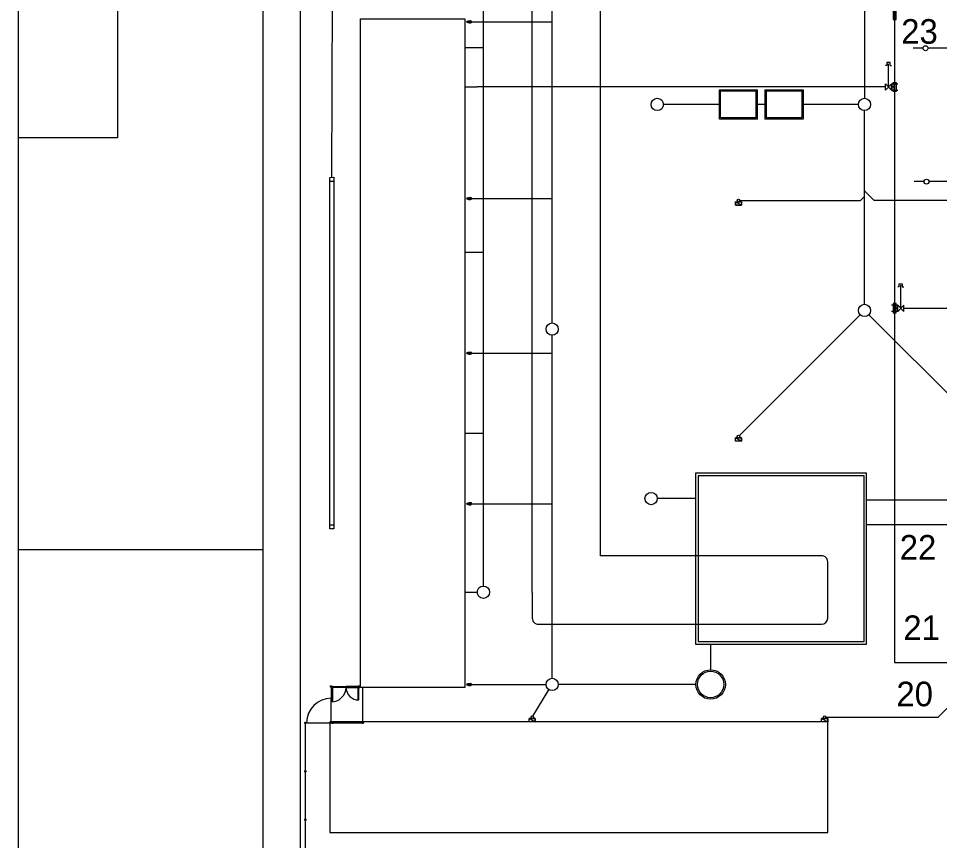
# Model space of a CAD drawing. Extents: x -263995 to -263575, y -1242437 to -1242140.
# Drawn here: x -263995.4 to -263920.5, y -1242264.6 to -1242197.8 of the extents above; entities that cross this region are included whole.
import ezdxf

# ---------------------------------------------------------------- set-up
doc = ezdxf.new("R2010")
doc.units = 0
for name, color, linetype in [('KFA_2D_SITUACIA_DSP', 7, 'Continuous'), ('KFA_BODY', 7, 'Continuous'), ('RAM_NA_TLAC_A3_1-1000', 7, 'Continuous')]:
    doc.layers.add(name, color=color, linetype=linetype)

msp = doc.modelspace()

# ---------------------------------------------------------------- linework, layer by layer
at = {"layer": 'KFA_2D_SITUACIA_DSP'}
for p, q in [((-263953.617, -1242244.458), (-263953.617, -1242140.046)), ((-263948.093, -1242140.046), (-263948.093, -1242241.458)), ((-263926.593, -1242155.252), (-263926.593, -1242204.252)), ((-263952, -1242222.527), (-263952, -1242182)), ((-263924.143, -1242185.14), (-263924.143, -1242250.14)), ((-263972.468, -1242294.032), (-263972.468, -1242187.932)), ((-263987.358, -1242190.982), (-263987.358, -1242207.482)), ((-263975.518, -1242290.982), (-263975.518, -1242190.982)), ((-263957.597, -1242243.932), (-263957.597, -1242193.383)), ((-263969.921, -1242210.683), (-263969.869, -1242195.133)), ((-263924.268, -1242197.107), (-263924.268, -1242197.857)), ((-263924.018, -1242197.857), (-263924.018, -1242197.107)), ((-263967.597, -1242197.782), (-263959.097, -1242197.782)), ((-263967.597, -1242252.182), (-263967.597, -1242197.782)), ((-263967.593, -1242252.182), (-263967.593, -1242197.782)), ((-263967.593, -1242197.782), (-263959.093, -1242197.782)), ((-263967.593, -1242197.782), (-263959.097, -1242197.782)), ((-263967.593, -1242252.182), (-263967.593, -1242197.782)), ((-263967.478, -1242197.782), (-263967.358, -1242197.782)), ((-263959.097, -1242197.782), (-263959.093, -1242252.182)), ((-263959.097, -1242197.782), (-263959.097, -1242252.182)), ((-263959.093, -1242197.782), (-263959.093, -1242252.182)), ((-263958.762, -1242197.962), (-263958.742, -1242197.942)), ((-263958.742, -1242197.942), (-263958.637, -1242197.942)), ((-263924.268, -1242197.857), (-263924.018, -1242197.857)), ((-263958.799, -1242197.962), (-263958.762, -1242197.962)), ((-263958.799, -1242198.102), (-263958.762, -1242198.102)), ((-263958.762, -1242198.102), (-263958.742, -1242198.122)), ((-263958.742, -1242198.122), (-263958.637, -1242198.122)), ((-263958.575, -1242198.032), (-263952, -1242198.032)), ((-263959.097, -1242200.132), (-263957.597, -1242200.132)), ((-263921.824, -1242200.182), (-263922.624, -1242200.182)), ((-263915.293, -1242200.182), (-263921.424, -1242200.182)), ((-263924.768, -1242201.582), (-263924.893, -1242201.582)), ((-263924.768, -1242201.332), (-263924.768, -1242201.582)), ((-263924.518, -1242201.332), (-263924.768, -1242201.332)), ((-263924.643, -1242203.332), (-263924.643, -1242201.457)), ((-263924.518, -1242201.582), (-263924.518, -1242201.332)), ((-263924.518, -1242201.582), (-263924.393, -1242201.582)), ((-263924.893, -1242203.582), (-263924.893, -1242203.082)), ((-263924.393, -1242203.082), (-263924.893, -1242203.582)), ((-263924.893, -1242203.082), (-263924.393, -1242203.582)), ((-263924.393, -1242203.582), (-263924.393, -1242203.082)), ((-263924.393, -1242203.082), (-263923.893, -1242203.082)), ((-263924.268, -1242203.707), (-263924.268, -1242202.957)), ((-263924.268, -1242202.957), (-263924.018, -1242202.957)), ((-263924.018, -1242202.957), (-263924.018, -1242203.707)), ((-263959.097, -1242203.332), (-263958.097, -1242203.332)), ((-263924.893, -1242203.332), (-263958.097, -1242203.332)), ((-263938.393, -1242203.552), (-263935.293, -1242203.552)), ((-263938.393, -1242205.952), (-263938.393, -1242203.552)), ((-263938.293, -1242205.852), (-263938.293, -1242203.652)), ((-263938.293, -1242203.652), (-263935.393, -1242203.652)), ((-263935.393, -1242205.852), (-263935.393, -1242203.652)), ((-263935.293, -1242205.952), (-263935.293, -1242203.552)), ((-263934.693, -1242203.552), (-263931.593, -1242203.552)), ((-263934.693, -1242203.552), (-263934.693, -1242205.952)), ((-263934.593, -1242203.652), (-263934.593, -1242205.852)), ((-263934.593, -1242203.652), (-263931.693, -1242203.652)), ((-263931.693, -1242203.652), (-263931.693, -1242205.852)), ((-263931.593, -1242203.552), (-263931.593, -1242205.952)), ((-263924.143, -1242203.332), (-263924.393, -1242203.332)), ((-263924.393, -1242203.332), (-263924.143, -1242203.332)), ((-263924.393, -1242203.582), (-263923.893, -1242203.582)), ((-263924.018, -1242203.707), (-263924.268, -1242203.707)), ((-263938.393, -1242204.752), (-263942.945, -1242204.752)), ((-263934.693, -1242204.752), (-263935.293, -1242204.752)), ((-263927.093, -1242204.752), (-263931.593, -1242204.752)), ((-263926.593, -1242221.011), (-263926.593, -1242205.252)), ((-263935.293, -1242205.952), (-263938.393, -1242205.952)), ((-263935.393, -1242205.852), (-263938.293, -1242205.852)), ((-263931.593, -1242205.952), (-263934.693, -1242205.952)), ((-263931.693, -1242205.852), (-263934.593, -1242205.852)), ((-263987.358, -1242207.482), (-263995.414, -1242207.482)), ((-263970.071, -1242210.684), (-263969.77, -1242210.682)), ((-263970.07, -1242239.282), (-263970.071, -1242210.684)), ((-263969.77, -1242210.682), (-263969.77, -1242239.282)), ((-263970.071, -1242210.983), (-263969.771, -1242210.985)), ((-263921.751, -1242211.032), (-263922.551, -1242211.032)), ((-263903.343, -1242211.032), (-263921.351, -1242211.032)), ((-263925.798, -1242212.562), (-263926.593, -1242211.767)), ((-263958.799, -1242212.337), (-263958.762, -1242212.337)), ((-263958.799, -1242212.477), (-263958.762, -1242212.477)), ((-263958.762, -1242212.337), (-263958.742, -1242212.317)), ((-263958.762, -1242212.477), (-263958.742, -1242212.497)), ((-263958.742, -1242212.317), (-263958.637, -1242212.317)), ((-263958.742, -1242212.497), (-263958.637, -1242212.497)), ((-263958.575, -1242212.407), (-263952, -1242212.407)), ((-263937.093, -1242212.952), (-263937.093, -1242212.662)), ((-263937.093, -1242212.662), (-263936.593, -1242212.662)), ((-263936.593, -1242212.952), (-263937.093, -1242212.662)), ((-263936.593, -1242212.952), (-263937.093, -1242212.662)), ((-263937.093, -1242212.662), (-263937.093, -1242212.952)), ((-263936.743, -1242212.562), (-263926.919, -1242212.562)), ((-263936.593, -1242212.662), (-263936.593, -1242212.952)), ((-263926.919, -1242212.562), (-263926.593, -1242212.237)), ((-263916.443, -1242212.562), (-263925.798, -1242212.562)), ((-263936.593, -1242212.952), (-263937.093, -1242212.952)), ((-263937.093, -1242212.952), (-263936.593, -1242212.952)), ((-263959.097, -1242216.782), (-263957.597, -1242216.782)), ((-263923.768, -1242219.582), (-263923.893, -1242219.582)), ((-263923.768, -1242219.582), (-263923.768, -1242219.332)), ((-263923.768, -1242219.332), (-263923.518, -1242219.332)), ((-263923.643, -1242221.332), (-263923.643, -1242219.457)), ((-263923.518, -1242219.332), (-263923.518, -1242219.582)), ((-263923.518, -1242219.582), (-263923.393, -1242219.582)), ((-263923.893, -1242221.082), (-263924.393, -1242221.082)), ((-263924.018, -1242220.957), (-263924.268, -1242220.957)), ((-263924.268, -1242220.957), (-263924.268, -1242221.707)), ((-263924.018, -1242221.707), (-263924.018, -1242220.957)), ((-263923.893, -1242221.582), (-263923.893, -1242221.082)), ((-263923.893, -1242221.082), (-263923.393, -1242221.582)), ((-263923.393, -1242221.082), (-263923.893, -1242221.582)), ((-263923.393, -1242221.582), (-263923.393, -1242221.082)), ((-263936.772, -1242231.691), (-263926.947, -1242221.865)), ((-263916.414, -1242231.691), (-263926.24, -1242221.865)), ((-263923.893, -1242221.582), (-263924.393, -1242221.582)), ((-263924.268, -1242221.707), (-263924.018, -1242221.707)), ((-263924.143, -1242221.332), (-263923.893, -1242221.332)), ((-263923.893, -1242221.332), (-263924.143, -1242221.332)), ((-263923.393, -1242221.332), (-263903.343, -1242221.332)), ((-263952, -1242251.432), (-263952, -1242223.527)), ((-263958.799, -1242224.912), (-263958.762, -1242224.912)), ((-263958.762, -1242224.912), (-263958.742, -1242224.892)), ((-263958.742, -1242224.892), (-263958.637, -1242224.892)), ((-263958.799, -1242225.052), (-263958.762, -1242225.052)), ((-263958.762, -1242225.052), (-263958.742, -1242225.072)), ((-263958.742, -1242225.072), (-263958.637, -1242225.072)), ((-263958.575, -1242224.982), (-263952, -1242224.982)), ((-263959.097, -1242231.482), (-263957.597, -1242231.482)), ((-263937.093, -1242231.862), (-263936.593, -1242231.862)), ((-263937.093, -1242232.152), (-263937.093, -1242231.862)), ((-263937.093, -1242231.862), (-263936.593, -1242232.152)), ((-263937.093, -1242231.862), (-263936.593, -1242232.152)), ((-263936.593, -1242231.862), (-263937.093, -1242231.862)), ((-263936.593, -1242232.152), (-263937.093, -1242232.152)), ((-263936.593, -1242231.862), (-263936.593, -1242232.152)), ((-263936.593, -1242232.152), (-263936.593, -1242231.862)), ((-263926.43, -1242234.749), (-263940.33, -1242234.749)), ((-263940.33, -1242234.749), (-263940.33, -1242248.649)), ((-263926.63, -1242234.949), (-263940.13, -1242234.949)), ((-263940.13, -1242234.949), (-263940.13, -1242248.449)), ((-263926.63, -1242248.449), (-263926.63, -1242234.949)), ((-263926.43, -1242248.649), (-263926.43, -1242234.749)), ((-263940.33, -1242236.811), (-263943.454, -1242236.811)), ((-263958.799, -1242237.162), (-263958.762, -1242237.162)), ((-263958.799, -1242237.302), (-263958.762, -1242237.302)), ((-263958.762, -1242237.162), (-263958.742, -1242237.142)), ((-263958.762, -1242237.302), (-263958.742, -1242237.322)), ((-263958.742, -1242237.142), (-263958.637, -1242237.142)), ((-263958.742, -1242237.322), (-263958.637, -1242237.322)), ((-263958.575, -1242237.232), (-263952, -1242237.232)), ((-263919.13, -1242236.949), (-263926.43, -1242236.949)), ((-263969.77, -1242238.982), (-263970.07, -1242238.982)), ((-263907.219, -1242238.949), (-263926.43, -1242238.949)), ((-263969.77, -1242239.282), (-263970.07, -1242239.282)), ((-263975.518, -1242240.982), (-263995.414, -1242240.982)), ((-263930.081, -1242241.458), (-263948.093, -1242241.458)), ((-263929.582, -1242246.53), (-263929.581, -1242241.959)), ((-263959.097, -1242244.432), (-263958.097, -1242244.432)), ((-263953.617, -1242244.458), (-263953.619, -1242246.529)), ((-263953.119, -1242247.03), (-263930.082, -1242247.03)), ((-263940.33, -1242248.649), (-263926.43, -1242248.649)), ((-263940.13, -1242248.449), (-263926.63, -1242248.449)), ((-263939.13, -1242248.649), (-263939.13, -1242250.737)), ((-263924.143, -1242250.14), (-263788.143, -1242250.14)), ((-263958.799, -1242251.862), (-263958.762, -1242251.862)), ((-263958.762, -1242251.862), (-263958.742, -1242251.842)), ((-263958.742, -1242251.842), (-263958.637, -1242251.842)), ((-263970.018, -1242252.152), (-263970.018, -1242252.052)), ((-263970.018, -1242252.052), (-263969.918, -1242252.052)), ((-263969.918, -1242252.152), (-263970.018, -1242252.152)), ((-263970.005, -1242252.14), (-263970.005, -1242252.065)), ((-263970.005, -1242252.065), (-263969.93, -1242252.065)), ((-263969.93, -1242252.14), (-263970.005, -1242252.14)), ((-263969.93, -1242252.14), (-263969.98, -1242252.14)), ((-263969.98, -1242252.14), (-263969.98, -1242252.24)), ((-263969.98, -1242252.24), (-263969.955, -1242252.24)), ((-263969.968, -1242252.152), (-263969.968, -1242252.202)), ((-263969.968, -1242252.202), (-263969.868, -1242252.202)), ((-263969.955, -1242253.327), (-263969.955, -1242252.19)), ((-263969.955, -1242252.19), (-263969.88, -1242252.19)), ((-263969.93, -1242252.065), (-263969.93, -1242252.14)), ((-263969.918, -1242252.052), (-263969.918, -1242252.152)), ((-263969.918, -1242252.102), (-263968.78, -1242252.102)), ((-263969.918, -1242252.177), (-263969.918, -1242252.102)), ((-263968.78, -1242252.177), (-263969.918, -1242252.177)), ((-263969.88, -1242252.19), (-263969.88, -1242253.327)), ((-263969.868, -1242252.202), (-263969.868, -1242252.177)), ((-263968.78, -1242252.102), (-263968.78, -1242252.177)), ((-263967.768, -1242252.102), (-263968.755, -1242252.102)), ((-263968.755, -1242252.102), (-263968.755, -1242252.177)), ((-263968.755, -1242252.177), (-263967.768, -1242252.177)), ((-263967.818, -1242252.202), (-263967.818, -1242252.177)), ((-263967.718, -1242252.202), (-263967.818, -1242252.202)), ((-263967.805, -1242252.19), (-263967.807, -1242253.177)), ((-263967.73, -1242252.19), (-263967.805, -1242252.19)), ((-263967.768, -1242252.152), (-263967.768, -1242252.052)), ((-263967.768, -1242252.052), (-263967.668, -1242252.052)), ((-263967.768, -1242252.177), (-263967.768, -1242252.102)), ((-263967.668, -1242252.152), (-263967.768, -1242252.152)), ((-263967.755, -1242252.14), (-263967.755, -1242252.065)), ((-263967.755, -1242252.065), (-263967.68, -1242252.065)), ((-263967.755, -1242252.14), (-263967.705, -1242252.14)), ((-263967.68, -1242252.14), (-263967.755, -1242252.14)), ((-263967.732, -1242253.177), (-263967.73, -1242252.19)), ((-263967.705, -1242252.24), (-263967.73, -1242252.24)), ((-263967.718, -1242252.152), (-263967.718, -1242252.202)), ((-263967.705, -1242252.14), (-263967.705, -1242252.24)), ((-263967.68, -1242252.065), (-263967.68, -1242252.14)), ((-263967.668, -1242252.052), (-263967.668, -1242252.152)), ((-263959.097, -1242252.182), (-263967.597, -1242252.182)), ((-263959.093, -1242252.182), (-263967.593, -1242252.182)), ((-263959.093, -1242252.182), (-263967.593, -1242252.182)), ((-263967.418, -1242252.182), (-263967.418, -1242255.057)), ((-263958.799, -1242252.002), (-263958.762, -1242252.002)), ((-263958.762, -1242252.002), (-263958.742, -1242252.022)), ((-263958.742, -1242252.022), (-263958.637, -1242252.022)), ((-263958.575, -1242251.932), (-263952.5, -1242251.932)), ((-263953.57, -1242254.506), (-263952.26, -1242252.359)), ((-263940.302, -1242251.932), (-263951.5, -1242251.932)), ((-263969.968, -1242255.057), (-263969.968, -1242253.057)), ((-263920.595, -1242254.592), (-263918.723, -1242252.72)), ((-263953.87, -1242254.692), (-263953.37, -1242254.692)), ((-263953.87, -1242254.982), (-263953.87, -1242254.692)), ((-263953.87, -1242254.692), (-263953.37, -1242254.982)), ((-263953.87, -1242254.692), (-263953.37, -1242254.982)), ((-263953.37, -1242254.692), (-263953.87, -1242254.692)), ((-263953.37, -1242254.692), (-263953.37, -1242254.982)), ((-263953.37, -1242254.982), (-263953.37, -1242254.692)), ((-263930.08, -1242254.692), (-263929.58, -1242254.692)), ((-263930.08, -1242254.982), (-263930.08, -1242254.692)), ((-263930.08, -1242254.692), (-263929.58, -1242254.982)), ((-263930.08, -1242254.692), (-263929.58, -1242254.982)), ((-263929.58, -1242254.692), (-263930.08, -1242254.692)), ((-263929.73, -1242254.592), (-263920.595, -1242254.592)), ((-263929.58, -1242254.692), (-263929.58, -1242254.982)), ((-263929.58, -1242254.982), (-263929.58, -1242254.692)), ((-263972.128, -1242255.057), (-263972.008, -1242255.057)), ((-263972.068, -1242255.117), (-263972.068, -1242254.997)), ((-263972.068, -1242255.057), (-263967.418, -1242255.057)), ((-263972.068, -1242294.432), (-263972.068, -1242255.057)), ((-263929.58, -1242254.982), (-263970.077, -1242254.982)), ((-263970.077, -1242254.982), (-263970.077, -1242263.982)), ((-263969.928, -1242255.057), (-263969.808, -1242255.057)), ((-263969.868, -1242255.117), (-263969.868, -1242254.997)), ((-263967.478, -1242255.057), (-263967.358, -1242255.057)), ((-263967.418, -1242255.117), (-263967.418, -1242254.997)), ((-263953.37, -1242254.982), (-263953.87, -1242254.982)), ((-263929.58, -1242254.982), (-263930.08, -1242254.982)), ((-263929.58, -1242263.982), (-263929.58, -1242254.982)), ((-263972.128, -1242258.995), (-263972.008, -1242258.995)), ((-263972.068, -1242259.055), (-263972.068, -1242258.935)), ((-263972.128, -1242262.932), (-263972.008, -1242262.932)), ((-263972.068, -1242262.992), (-263972.068, -1242262.872)), ((-263970.077, -1242263.982), (-263929.58, -1242263.982))]:
    msp.add_line(p, q, dxfattribs=at)
for centre, radius in [((-263958.847, -1242198.032), 0.085), ((-263958.847, -1242198.032), 0.0625), ((-263958.637, -1242198.032), 0.0625), ((-263921.624, -1242200.182), 0.2), ((-263943.445, -1242204.752), 0.5), ((-263926.593, -1242204.752), 0.5), ((-263921.551, -1242211.032), 0.2), ((-263958.847, -1242212.407), 0.085), ((-263958.847, -1242212.407), 0.0625), ((-263958.637, -1242212.407), 0.0625), ((-263936.843, -1242212.562), 0.1), ((-263926.593, -1242221.511), 0.5), ((-263952, -1242223.027), 0.5), ((-263958.847, -1242224.982), 0.085), ((-263958.847, -1242224.982), 0.0625), ((-263958.637, -1242224.982), 0.0625), ((-263936.843, -1242231.762), 0.1), ((-263943.954, -1242236.811), 0.5), ((-263958.847, -1242237.232), 0.085), ((-263958.847, -1242237.232), 0.0625), ((-263958.637, -1242237.232), 0.0625), ((-263957.597, -1242244.432), 0.5), ((-263939.107, -1242251.932), 1.195), ((-263939.107, -1242251.932), 1.075), ((-263958.847, -1242251.932), 0.085), ((-263958.847, -1242251.932), 0.0625), ((-263958.637, -1242251.932), 0.0625), ((-263952, -1242251.932), 0.5), ((-263953.62, -1242254.592), 0.1), ((-263929.83, -1242254.592), 0.1), ((-263972.068, -1242255.057), 0.06), ((-263969.868, -1242255.057), 0.06), ((-263967.418, -1242255.057), 0.06), ((-263972.068, -1242258.995), 0.06), ((-263972.068, -1242262.932), 0.06)]:
    msp.add_circle(centre, radius, dxfattribs=at)
for centre, radius, start, end in [((-263958.637, -1242198.032), 0.09, 270, 90), ((-263958.637, -1242212.407), 0.09, 270, 90), ((-263958.637, -1242224.982), 0.09, 270, 90), ((-263958.637, -1242237.232), 0.09, 270, 90), ((-263930.081, -1242241.958), 0.5, 359.97854, 89.99994), ((-263953.119, -1242246.53), 0.5, 179.95255, 270), ((-263930.082, -1242246.53), 0.5, 270, 359.97854), ((-263958.637, -1242251.932), 0.09, 270, 90), ((-263969.943, -1242252.165), 1.175, 269.39046, 359.39047), ((-263967.743, -1242252.165), 1.025, 180.60953, 270.60954), ((-263969.968, -1242255.057), 2, 90, 180)]:
    msp.add_arc(centre, radius, start, end, dxfattribs=at)
for centre in [(-263969.943, -1242252.165), (-263969.943, -1242252.165), (-263967.743, -1242252.165)]:
    msp.add_ellipse(centre, major_axis=(0, 0.0125), ratio=0.999995, dxfattribs=at)
at = {"layer": 'RAM_NA_TLAC_A3_1-1000'}
msp.add_lwpolyline([(-263995.414, -1242140.046), (-263575.414, -1242140.046), (-263575.414, -1242437.046), (-263995.414, -1242437.046)], close=True, dxfattribs=at)

# ---------------------------------------------------------------- texts
at = {"layer": 'KFA_BODY'}
for s, p in [('23', (-263923.606, -1242199.815)), ('22', (-263923.728, -1242241.775)), ('21', (-263923.435, -1242248.317)), ('20', (-263923.999, -1242253.704))]:
    msp.add_text(s, height=2, dxfattribs=at).set_placement(p)

doc.saveas('drawing.dxf')
